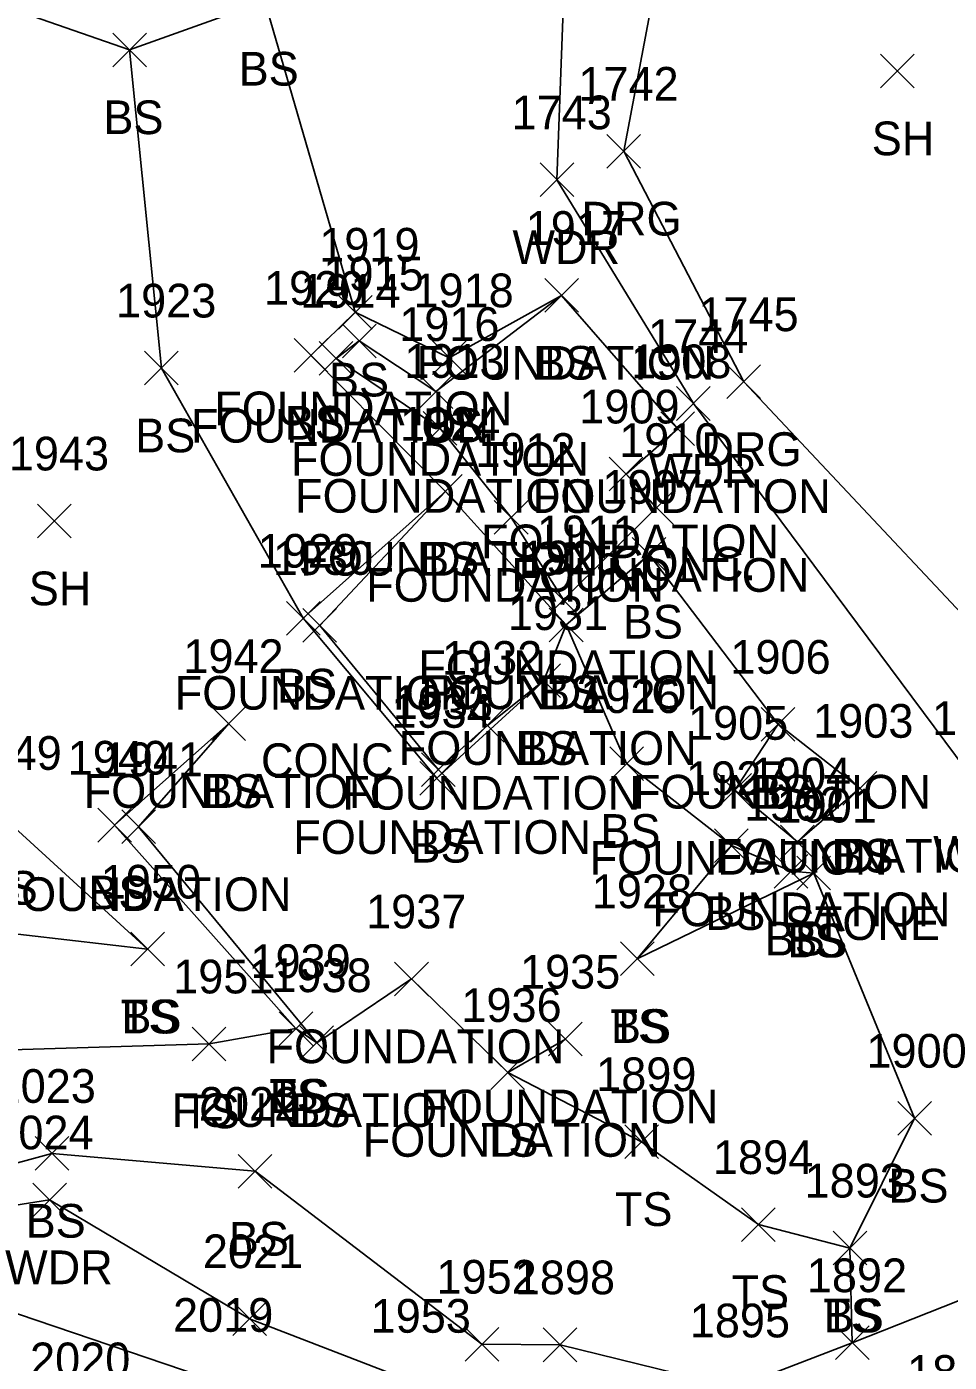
# Model space of a CAD drawing. Extents: x 1600281 to 1602254, y 862855 to 863227.
# Drawn here: x 1601993.2 to 1602048, y 863101.9 to 863181.1 of the extents above; entities that cross this region are included whole.
import ezdxf

# ---------------------------------------------------------------- set-up
doc = ezdxf.new("R2010")
doc.units = 0
for name, color, linetype in [('L_A', 7, 'Continuous'), ('L_C', 7, 'Continuous'), ('L_I', 7, 'Continuous'), ('L_TIC', 7, 'Continuous'), ('LAWA', 7, 'Continuous'), ('LAWE', 7, 'Continuous'), ('LBC', 7, 'Continuous'), ('LELB', 7, 'Continuous'), ('LSOGP', 7, 'Continuous'), ('R_A', 7, 'Continuous'), ('R_I', 7, 'Continuous'), ('R_TIC', 7, 'Continuous'), ('RDG', 7, 'Continuous')]:
    doc.layers.add(name, color=color, linetype=linetype)

msp = doc.modelspace()

# ---------------------------------------------------------------- linework, layer by layer
at = {"layer": 'L_TIC'}
for points in [[(1601998.337, 863178.726), (1602000.337, 863180.726)], [(1602000.337, 863178.726), (1601998.337, 863180.726)], [(1602043.887, 863177.474), (1602045.887, 863179.474)], [(1602045.887, 863177.474), (1602043.887, 863179.474)], [(1602023.692, 863171.016), (1602025.692, 863173.016)], [(1602025.692, 863171.016), (1602023.692, 863173.016)], [(1602023.966, 863164.156), (1602025.966, 863166.156)], [(1602025.966, 863164.156), (1602023.966, 863166.156)], [(1602023.966, 863164.156), (1602025.966, 863166.156)], [(1602025.966, 863164.156), (1602023.966, 863166.156)], [(1602023.966, 863164.156), (1602025.966, 863166.156)], [(1602025.966, 863164.156), (1602023.966, 863166.156)], [(1602011.721, 863163.161), (1602013.721, 863165.161)], [(1602013.721, 863163.161), (1602011.721, 863165.161)], [(1602011.721, 863163.161), (1602013.721, 863165.161)], [(1602013.721, 863163.161), (1602011.721, 863165.161)], [(1602011.964, 863161.452), (1602013.964, 863163.452)], [(1602013.964, 863161.452), (1602011.964, 863163.452)], [(1602009.09, 863160.598), (1602011.09, 863162.598)], [(1602011.09, 863160.598), (1602009.09, 863162.598)], [(1602010.587, 863160.423), (1602012.587, 863162.423)], [(1602012.587, 863160.423), (1602010.587, 863162.423)], [(1602017.304, 863160.454), (1602019.304, 863162.454)], [(1602019.304, 863160.454), (1602017.304, 863162.454)], [(1602000.222, 863159.847), (1602002.222, 863161.847)], [(1602002.222, 863159.847), (1602000.222, 863161.847)], [(1602016.514, 863158.452), (1602018.514, 863160.452)], [(1602018.514, 863158.452), (1602016.514, 863160.452)], [(1602031.794, 863157.744), (1602033.794, 863159.744)], [(1602033.794, 863157.744), (1602031.794, 863159.744)], [(1602016.762, 863156.264), (1602018.762, 863158.264)], [(1602018.762, 863156.264), (1602016.762, 863158.264)], [(1602030.865, 863156.245), (1602032.865, 863158.245)], [(1602032.865, 863156.245), (1602030.865, 863158.245)], [(1602030.865, 863156.245), (1602032.865, 863158.245)], [(1602032.865, 863156.245), (1602030.865, 863158.245)], [(1602027.795, 863153.559), (1602029.795, 863155.559)], [(1602029.795, 863153.559), (1602027.795, 863155.559)], [(1602017.074, 863152.53), (1602019.074, 863154.53)], [(1602019.074, 863152.53), (1602017.074, 863154.53)], [(1602017.074, 863152.53), (1602019.074, 863154.53)], [(1602019.074, 863152.53), (1602017.074, 863154.53)], [(1602017.074, 863152.53), (1602019.074, 863154.53)], [(1602019.074, 863152.53), (1602017.074, 863154.53)], [(1602029.6, 863151.569), (1602031.6, 863153.569)], [(1602031.6, 863151.569), (1602029.6, 863153.569)], [(1601993.86, 863150.771), (1601995.86, 863152.771)], [(1601995.86, 863150.771), (1601993.86, 863152.771)], [(1602020.977, 863150.982), (1602022.977, 863152.982)], [(1602022.977, 863150.982), (1602020.977, 863152.982)], [(1602029.161, 863148.793), (1602031.161, 863150.793)], [(1602031.161, 863148.793), (1602029.161, 863150.793)], [(1602024.073, 863146.091), (1602026.073, 863148.091)], [(1602026.073, 863146.091), (1602024.073, 863148.091)], [(1602008.637, 863145.001), (1602010.637, 863147.001)], [(1602010.637, 863145.001), (1602008.637, 863147.001)], [(1602008.637, 863145.001), (1602010.637, 863147.001)], [(1602010.637, 863145.001), (1602008.637, 863147.001)], [(1602009.618, 863144.576), (1602011.618, 863146.576)], [(1602011.618, 863144.576), (1602009.618, 863146.576)], [(1602024.241, 863144.606), (1602026.241, 863146.606)], [(1602026.241, 863144.606), (1602024.241, 863146.606)], [(1602024.241, 863144.606), (1602026.241, 863146.606)], [(1602026.241, 863144.606), (1602024.241, 863146.606)], [(1602022.912, 863141.301), (1602024.912, 863143.301)], [(1602024.912, 863141.301), (1602022.912, 863143.301)], [(1602022.912, 863141.301), (1602024.912, 863143.301)], [(1602024.912, 863141.301), (1602022.912, 863143.301)], [(1602004.216, 863138.75), (1602006.216, 863140.75)], [(1602006.216, 863138.75), (1602004.216, 863140.75)], [(1602004.216, 863138.75), (1602006.216, 863140.75)], [(1602006.216, 863138.75), (1602004.216, 863140.75)], [(1602019.565, 863138.645), (1602021.565, 863140.645)], [(1602021.565, 863138.645), (1602019.565, 863140.645)], [(1602036.811, 863138.707), (1602038.811, 863140.707)], [(1602038.811, 863138.707), (1602036.811, 863140.707)], [(1602036.811, 863138.707), (1602038.811, 863140.707)], [(1602038.811, 863138.707), (1602036.811, 863140.707)], [(1602016.649, 863136.018), (1602018.649, 863138.018)], [(1602018.649, 863136.018), (1602016.649, 863138.018)], [(1602016.649, 863136.018), (1602018.649, 863138.018)], [(1602018.649, 863136.018), (1602016.649, 863138.018)], [(1602027.826, 863136.378), (1602029.826, 863138.378)], [(1602029.826, 863136.378), (1602027.826, 863138.378)], [(1602016.564, 863135.502), (1602018.564, 863137.502)], [(1602018.564, 863135.502), (1602016.564, 863137.502)], [(1602016.564, 863135.502), (1602018.564, 863137.502)], [(1602018.564, 863135.502), (1602016.564, 863137.502)], [(1602041.668, 863134.91), (1602043.668, 863136.91)], [(1602043.668, 863134.91), (1602041.668, 863136.91)], [(1602041.668, 863134.91), (1602043.668, 863136.91)], [(1602043.668, 863134.91), (1602041.668, 863136.91)], [(1602034.24, 863134.79), (1602036.24, 863136.79)], [(1602036.24, 863134.79), (1602034.24, 863136.79)], [(1601997.441, 863132.724), (1601999.441, 863134.724)], [(1601999.441, 863132.724), (1601997.441, 863134.724)], [(1601998.867, 863132.629), (1602000.867, 863134.629)], [(1602000.867, 863132.629), (1601998.867, 863134.629)], [(1602037.966, 863131.728), (1602039.966, 863133.728)], [(1602039.966, 863131.728), (1602037.966, 863133.728)], [(1602034.05, 863131.509), (1602036.05, 863133.509)], [(1602036.05, 863131.509), (1602034.05, 863133.509)], [(1602034.05, 863131.509), (1602036.05, 863133.509)], [(1602036.05, 863131.509), (1602034.05, 863133.509)], [(1602037.579, 863129.992), (1602039.579, 863131.992)], [(1602039.579, 863129.992), (1602037.579, 863131.992)], [(1602038.931, 863129.88), (1602040.931, 863131.88)], [(1602040.931, 863129.88), (1602038.931, 863131.88)], [(1602038.931, 863129.88), (1602040.931, 863131.88)], [(1602040.931, 863129.88), (1602038.931, 863131.88)], [(1601999.402, 863125.367), (1602001.402, 863127.367)], [(1602001.402, 863125.367), (1601999.402, 863127.367)], [(1601999.402, 863125.367), (1602001.402, 863127.367)], [(1602001.402, 863125.367), (1601999.402, 863127.367)], [(1602028.455, 863124.798), (1602030.455, 863126.798)], [(1602030.455, 863124.798), (1602028.455, 863126.798)], [(1602028.455, 863124.798), (1602030.455, 863126.798)], [(1602030.455, 863124.798), (1602028.455, 863126.798)], [(1602015.062, 863123.599), (1602017.062, 863125.599)], [(1602017.062, 863123.599), (1602015.062, 863125.599)], [(1602008.208, 863120.652), (1602010.208, 863122.652)], [(1602010.208, 863120.652), (1602008.208, 863122.652)], [(1602008.208, 863120.652), (1602010.208, 863122.652)], [(1602010.208, 863120.652), (1602008.208, 863122.652)], [(1602009.439, 863119.816), (1602011.439, 863121.816)], [(1602011.439, 863119.816), (1602009.439, 863121.816)], [(1602009.439, 863119.816), (1602011.439, 863121.816)], [(1602011.439, 863119.816), (1602009.439, 863121.816)], [(1602024.193, 863120.028), (1602026.193, 863122.028)], [(1602026.193, 863120.028), (1602024.193, 863122.028)], [(1602003.047, 863119.74), (1602005.047, 863121.74)], [(1602005.047, 863119.74), (1602003.047, 863121.74)], [(1602020.769, 863118.047), (1602022.769, 863120.047)], [(1602022.769, 863118.047), (1602020.769, 863120.047)], [(1602020.769, 863118.047), (1602022.769, 863120.047)], [(1602022.769, 863118.047), (1602020.769, 863120.047)], [(1602044.92, 863115.332), (1602046.92, 863117.332)], [(1602046.92, 863115.332), (1602044.92, 863117.332)], [(1602028.72, 863113.941), (1602030.72, 863115.941)], [(1602030.72, 863113.941), (1602028.72, 863115.941)], [(1601993.721, 863113.246), (1601995.721, 863115.246)], [(1601995.721, 863113.246), (1601993.721, 863115.246)], [(1602005.781, 863112.183), (1602007.781, 863114.183)], [(1602007.781, 863112.183), (1602005.781, 863114.183)], [(1601993.585, 863110.487), (1601995.585, 863112.487)], [(1601995.585, 863110.487), (1601993.585, 863112.487)], [(1602035.644, 863109.021), (1602037.644, 863111.021)], [(1602037.644, 863109.021), (1602035.644, 863111.021)], [(1602041.083, 863107.629), (1602043.083, 863109.629)], [(1602043.083, 863107.629), (1602041.083, 863109.629)], [(1602041.083, 863107.629), (1602043.083, 863109.629)], [(1602043.083, 863107.629), (1602041.083, 863109.629)], [(1602005.455, 863103.438), (1602007.455, 863105.438)], [(1602007.455, 863103.438), (1602005.455, 863105.438)], [(1602019.237, 863101.925), (1602021.237, 863103.925)], [(1602021.237, 863101.925), (1602019.237, 863103.925)], [(1602023.883, 863101.888), (1602025.883, 863103.888)], [(1602025.883, 863101.888), (1602023.883, 863103.888)], [(1602041.214, 863102.013), (1602043.214, 863104.013)], [(1602043.214, 863102.013), (1602041.214, 863104.013)], [(1602041.214, 863102.013), (1602043.214, 863104.013)], [(1602043.214, 863102.013), (1602041.214, 863104.013)]]:
    msp.add_lwpolyline(points, dxfattribs=at)
at = {"layer": 'LAWA'}
for points in [[(1602117.191, 863138.117), (1602108.93, 863139.196), (1602098.439, 863147.474), (1602087.128, 863158.967), (1602081.34, 863183), (1602074.275, 863197.396), (1602065.047, 863221.998), (1602049.133, 863212.707), (1602032.105, 863201.55), (1602028.2, 863197.002), (1602026.665, 863194.298), (1602025.937, 863190.594), (1602025.234, 863186.894), (1602024.692, 863172.016), (1602032.794, 863158.744), (1602049.66, 863136.076), (1602061.607, 863128.634), (1602064.822, 863129.779), (1602064.976, 863118.423), (1602058.16, 863113.919), (1602052.162, 863106.946), (1602042.214, 863103.013), (1602035.268, 863100.33)], [(1602016.33, 863100.607), (1602006.455, 863104.438), (1601994.585, 863111.487), (1601987.829, 863110.416), (1601981.429, 863103.605), (1601971.238, 863106.008), (1601967.104, 863111.38), (1601958.937, 863111.828), (1601954.923, 863115.051), (1601946.135, 863119.327), (1601936.521, 863120.508), (1601930.523, 863138.372), (1601920.688, 863148.407)]]:
    msp.add_lwpolyline(points, dxfattribs=at)
at = {"layer": 'LAWE'}
msp.add_lwpolyline([(1602053.378, 863085.572), (1602049.014, 863088.599), (1602037.877, 863092.461), (1602027.14, 863095.153), (1602014.534, 863094.667), (1602004.691, 863100.661), (1601989.462, 863105.807), (1601980.589, 863100.305)], dxfattribs=at)
at = {"layer": 'LBC'}
for points in [[(1602031.865, 863157.245), (1602028.795, 863154.559), (1602030.6, 863152.569), (1602025.073, 863147.091), (1602021.977, 863151.982), (1602017.762, 863157.264), (1602011.587, 863161.423), (1602012.964, 863162.452), (1602017.514, 863159.452), (1602024.966, 863165.156)], [(1602031.865, 863157.245), (1602024.966, 863165.156)], [(1602018.074, 863153.53), (1602010.618, 863145.576), (1602017.649, 863137.018)], [(1602018.074, 863153.53), (1602025.241, 863145.606), (1602023.912, 863142.301), (1602020.565, 863139.645), (1602017.649, 863137.018)], [(1602025.193, 863121.028), (1602021.769, 863119.047), (1602016.062, 863124.599), (1602010.439, 863120.816), (1601999.867, 863133.629), (1602005.216, 863139.75)], [(1602042.668, 863135.91), (1602038.966, 863132.728), (1602035.24, 863135.79), (1602037.811, 863139.707)]]:
    msp.add_lwpolyline(points, dxfattribs=at)
at = {"layer": 'LELB'}
for points in [[(1601957.22, 863184.57), (1601969.644, 863166.44), (1601979.328, 863149.611), (1601992.057, 863134.005), (1602000.402, 863126.367)], [(1602012.721, 863164.161), (1602007.362, 863182.606), (1601999.337, 863179.726), (1602001.222, 863160.847), (1602009.637, 863146.001)], [(1602000.402, 863126.367), (1601986.007, 863128.021), (1601972.131, 863136.924), (1601960.048, 863139.675), (1601951.483, 863151.649), (1601933.606, 863167.485)], [(1602024.966, 863165.156), (1602018.304, 863161.454), (1602012.721, 863164.161), (1602010.09, 863161.598), (1602018.074, 863153.53), (1602009.637, 863146.001), (1602017.564, 863136.502)], [(1602009.208, 863121.652), (1602004.047, 863120.74), (1601989.013, 863120.288), (1601977.559, 863125.375), (1601970.085, 863125.83), (1601965.747, 863121.079), (1601954.923, 863115.051), (1601954.28, 863126.538), (1601948.043, 863135.984), (1601939.077, 863144.14), (1601930.07, 863156.542)], [(1602042.668, 863135.91), (1602037.811, 863139.707), (1602030.161, 863149.793), (1602025.241, 863145.606), (1602028.826, 863137.378), (1602035.05, 863132.509)], [(1602023.912, 863142.301), (1602017.564, 863136.502)], [(1602035.268, 863100.33), (1602024.883, 863102.888), (1602020.237, 863102.925), (1602006.781, 863113.183), (1601994.721, 863114.246), (1601987.36, 863112.239), (1601977.428, 863113.016), (1601970.299, 863112.715), (1601965.747, 863121.079), (1601960.048, 863139.675)], [(1602010.439, 863120.816), (1602009.208, 863121.652), (1601998.441, 863133.724), (1602005.216, 863139.75)], [(1602042.214, 863103.013), (1602042.083, 863108.629), (1602045.92, 863116.332), (1602039.931, 863130.88), (1602038.579, 863130.992), (1602035.05, 863132.509), (1602029.455, 863125.798)], [(1602039.931, 863130.88), (1602029.455, 863125.798)], [(1602042.083, 863108.629), (1602036.644, 863110.021), (1602029.72, 863114.941), (1602021.769, 863119.047)]]:
    msp.add_lwpolyline(points, dxfattribs=at)
at = {"layer": 'LSOGP'}
msp.add_lwpolyline([(1602125.538, 863173.403), (1602109.275, 863175.062), (1602106.49, 863191.711), (1602074.275, 863197.396), (1602065.047, 863221.998), (1602049.133, 863212.707), (1602032.105, 863201.55), (1602028.2, 863197.002), (1602026.665, 863194.298), (1602025.937, 863190.594), (1602025.234, 863186.894), (1602007.362, 863182.606), (1601999.337, 863179.726), (1601966.602, 863191.094), (1601957.22, 863184.57), (1601933.606, 863167.485), (1601930.07, 863156.542), (1601924.031, 863153.206)], dxfattribs=at)
at = {"layer": 'R_TIC'}
for points in [[(1602027.658, 863172.712), (1602029.658, 863174.712)], [(1602029.658, 863172.712), (1602027.658, 863174.712)], [(1602034.777, 863159.035), (1602036.777, 863161.035)], [(1602036.777, 863159.035), (1602034.777, 863161.035)]]:
    msp.add_lwpolyline(points, dxfattribs=at)
at = {"layer": 'RDG'}
msp.add_lwpolyline([(1602096.314, 863123.237), (1602095.851, 863125.022), (1602094.922, 863127.701), (1602091.394, 863132.436), (1602080.771, 863146.091), (1602073.916, 863167.679), (1602068.483, 863189.633), (1602064.495, 863203.426), (1602049.949, 863202.722), (1602036.232, 863194.16), (1602033.599, 863191.505), (1602032.5, 863189.602), (1602031.273, 863187.553), (1602028.658, 863173.712), (1602035.777, 863160.035), (1602055.152, 863139.425), (1602064.822, 863129.779), (1602067.689, 863122.351), (1602069.706, 863119.916), (1602071.558, 863117.437), (1602075.424, 863112.315)], dxfattribs=at)

# ---------------------------------------------------------------- texts
at = {"layer": 'L_A'}
for s, p in [('BS', (1602005.803, 863177.606)), ('BS', (1601997.778, 863174.726)), ('SH', (1602043.375, 863173.474)), ('WDR', (1602022.055, 863167.016)), ('FOUNDATION', (1602016.359, 863160.156)), ('FOUNDATION', (1602016.359, 863160.156)), ('BS', (1602023.407, 863160.156)), ('BS', (1602011.162, 863159.161)), ('BS', (1602011.162, 863159.161)), ('FOUNDATION', (1602004.358, 863157.452)), ('FOUNDATION', (1602002.98, 863156.423)), ('BS', (1602008.531, 863156.598)), ('BS', (1602016.745, 863156.454)), ('BS', (1601999.663, 863155.847)), ('FOUNDATION', (1602008.908, 863154.452)), ('WDR', (1602030.156, 863153.744)), ('FOUNDATION', (1602009.155, 863152.264)), ('FOUNDATION', (1602023.259, 863152.245)), ('FOUNDATION', (1602023.259, 863152.245)), ('FOUNDATION', (1602020.189, 863149.559)), ('FOUNDATION', (1602009.467, 863148.53)), ('FOUNDATION', (1602009.467, 863148.53)), ('BS', (1602016.515, 863148.53)), ('FOUNDATION', (1602021.994, 863147.569)), ('SH', (1601993.349, 863146.771)), ('FOUNDATION', (1602013.371, 863146.982)), ('BS', (1602028.602, 863144.793)), ('FOUNDATION', (1602016.467, 863142.091)), ('FOUNDATION', (1602002.012, 863140.576)), ('BS', (1602008.078, 863141.001)), ('BS', (1602008.078, 863141.001)), ('FOUNDATION', (1602016.635, 863140.606)), ('BS', (1602023.682, 863140.606)), ('FOUNDATION', (1602015.306, 863137.301)), ('BS', (1602022.353, 863137.301)), ('FOUNDATION', (1601996.61, 863134.75)), ('BS', (1602003.657, 863134.75)), ('FOUNDATION', (1602011.959, 863134.645)), ('FOUNDATION', (1602029.205, 863134.707)), ('BS', (1602036.252, 863134.707)), ('FOUNDATION', (1602009.043, 863132.018)), ('FOUNDATION', (1602009.043, 863132.018)), ('BS', (1602027.267, 863132.378)), ('BS', (1602016.005, 863131.502)), ('BS', (1602016.005, 863131.502)), ('FOUNDATION', (1602034.062, 863130.91)), ('BS', (1602041.109, 863130.91)), ('WDR', (1602047.022, 863131.076)), ('FOUNDATION', (1602026.634, 863130.79)), ('TS', (1601990.466, 863129.005)), ('FOUNDATION', (1601991.261, 863128.629)), ('BS', (1601996.882, 863128.724)), ('FOUNDATION', (1602030.359, 863127.728)), ('BS', (1602033.491, 863127.509)), ('BS', (1602033.491, 863127.509)), ('BS', (1602037.02, 863125.992)), ('TS', (1602038.34, 863125.88)), ('BS', (1602038.372, 863125.88)), ('TS', (1601998.812, 863121.367)), ('BS', (1601998.843, 863121.367)), ('TS', (1602027.864, 863120.798)), ('BS', (1602027.896, 863120.798)), ('FOUNDATION', (1602007.456, 863119.599)), ('TS', (1602007.618, 863116.652)), ('BS', (1602007.649, 863116.652)), ('FOUNDATION', (1602001.833, 863115.816)), ('BS', (1602008.88, 863115.816)), ('FOUNDATION', (1602016.586, 863116.028)), ('TS', (1602002.456, 863115.74)), ('FOUNDATION', (1602013.163, 863114.047)), ('TS', (1602020.179, 863114.047)), ('BS', (1602044.361, 863111.332)), ('TS', (1602028.13, 863109.941)), ('BS', (1601993.162, 863109.246)), ('BS', (1602005.221, 863108.183)), ('WDR', (1601991.947, 863106.487)), ('TS', (1602035.053, 863105.021)), ('TS', (1602040.493, 863103.629)), ('BS', (1602040.524, 863103.629))]:
    msp.add_text(s, height=2, dxfattribs=at).set_placement(p)
at = {"layer": 'L_C'}
for s, p in [('CONC.', (1602027.896, 863148.245)), ('CONC.', (1602027.896, 863148.245)), ('CONC', (1602007.13, 863136.576)), ('STONE', (1602038.212, 863126.91)), ('STONE', (1602038.212, 863126.91))]:
    msp.add_text(s, height=2, dxfattribs=at).set_placement(p)
at = {"layer": 'L_I'}
for s, p in [('1743', (1602022, 863175.016)), ('1917', (1602022.84, 863168.156)), ('1917', (1602022.84, 863168.156)), ('1917', (1602022.84, 863168.156)), ('1919', (1602010.587, 863167.161)), ('1919', (1602010.587, 863167.161)), ('1915', (1602010.838, 863165.452)), ('1920', (1602007.311, 863164.598)), ('1914', (1602009.461, 863164.423)), ('1918', (1602016.178, 863164.454)), ('1923', (1601998.529, 863163.847)), ('1916', (1602015.333, 863162.452)), ('1744', (1602030.101, 863161.744)), ('1913', (1602015.636, 863160.264)), ('1908', (1602029.093, 863160.245)), ('1908', (1602029.093, 863160.245)), ('1909', (1602026.016, 863157.559)), ('1924', (1602015.381, 863156.53)), ('1924', (1602015.381, 863156.53)), ('1924', (1602015.381, 863156.53)), ('1910', (1602028.388, 863155.569)), ('1943', (1601992.168, 863154.771)), ('1912', (1602019.851, 863154.982)), ('1907', (1602027.389, 863152.793)), ('1911', (1602023.514, 863150.091)), ('1929', (1602006.936, 863149.001)), ('1929', (1602006.936, 863149.001)), ('1930', (1602007.839, 863148.576)), ('1925', (1602022.548, 863148.606)), ('1925', (1602022.548, 863148.606)), ('1931', (1602021.786, 863145.301)), ('1931', (1602021.786, 863145.301)), ('1942', (1602002.523, 863142.75)), ('1942', (1602002.523, 863142.75)), ('1932', (1602017.873, 863142.645)), ('1906', (1602034.984, 863142.707)), ('1906', (1602034.984, 863142.707)), ('1926', (1602026.078, 863140.378)), ('1933', (1602014.956, 863140.018)), ('1933', (1602014.956, 863140.018)), ('1934', (1602014.871, 863139.502)), ('1934', (1602014.871, 863139.502)), ('1905', (1602032.469, 863138.79)), ('1903', (1602039.897, 863138.91)), ('1903', (1602039.897, 863138.91)), ('1749', (1602046.959, 863139.076)), ('1749', (1602046.959, 863139.076)), ('1949', (1601989.356, 863137.005)), ('1940', (1601995.661, 863136.724)), ('1941', (1601997.741, 863136.629)), ('1904', (1602036.194, 863135.728)), ('1927', (1602032.357, 863135.509)), ('1927', (1602032.357, 863135.509)), ('1902', (1602035.807, 863133.992)), ('1901', (1602037.726, 863133.88)), ('1901', (1602037.726, 863133.88)), ('1950', (1601997.623, 863129.367)), ('1950', (1601997.623, 863129.367)), ('1928', (1602026.762, 863128.798)), ('1928', (1602026.762, 863128.798)), ('1937', (1602013.369, 863127.599)), ('1939', (1602006.507, 863124.652)), ('1939', (1602006.507, 863124.652)), ('1951', (1602001.921, 863123.74)), ('1938', (1602007.747, 863123.816)), ('1938', (1602007.747, 863123.816)), ('1935', (1602022.5, 863124.028)), ('1936', (1602019.021, 863122.047)), ('1936', (1602019.021, 863122.047)), ('1900', (1602043.062, 863119.332)), ('1899', (1602027.019, 863117.941)), ('2023', (1601991.383, 863117.246)), ('2022', (1602003.442, 863116.183)), ('2024', (1601991.246, 863114.487)), ('1894', (1602033.951, 863113.021)), ('1893', (1602039.39, 863111.629)), ('1893', (1602039.39, 863111.629)), ('2021', (1602003.683, 863107.438)), ('1952', (1602017.544, 863105.925)), ('1898', (1602022.19, 863105.888)), ('1892', (1602039.521, 863106.013)), ('1892', (1602039.521, 863106.013)), ('2019', (1602001.912, 863103.661)), ('1953', (1602013.637, 863103.607)), ('1895', (1602032.575, 863103.33)), ('1895', (1602032.575, 863103.33)), ('2020', (1601993.425, 863101.022)), ('1889', (1602045.475, 863100.278))]:
    msp.add_text(s, height=2, dxfattribs=at).set_placement(p)
at = {"layer": 'R_A'}
for p in [(1602026.146, 863168.712), (1602033.265, 863155.035)]:
    msp.add_text('DRG', height=2, dxfattribs=at).set_placement(p)
at = {"layer": 'R_I'}
for s, p in [('1742', (1602025.965, 863176.712)), ('1745', (1602033.084, 863163.035))]:
    msp.add_text(s, height=2, dxfattribs=at).set_placement(p)

doc.saveas('drawing.dxf')
